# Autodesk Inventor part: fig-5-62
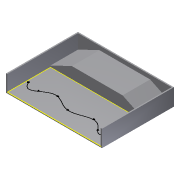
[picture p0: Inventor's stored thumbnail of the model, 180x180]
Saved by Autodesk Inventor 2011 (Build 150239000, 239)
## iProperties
Created: 2004-05
Part Number: fig-5-62
Document SubType Name: Modeling
Designer: CADCIM Technologies
Manufacturer: Standard
Standards Organization: Custom
Density: 1 g/cm^3
Author: CADCIM Technologies
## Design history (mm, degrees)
sketch "Sketch1"
  geometry: L1 (-40, -30)-(40, -30); L2 (40, -30)-(40, 30); L3 (40, 30)-(-40, 30); L4 (-40, 30)-(-40, -30); 1 further point
  constraints: 8 end point, 2 parallel, 1 horizontal, 1 perpendicular, 1 other
  dimensions: "d0" = 80 distance of L1.start L1.end; "d1" = 60 distance of L3.end L1.start; "d2" = 30 distance from line of point (0, 0) L1; "d3" = 40 distance from line of point (0, 0) L4
extrude "Extrusion1" new body sketch "Sketch1" distance "d4" = 14; taper "d5" = 0 deg
shell "Shell1" dims "d6" = 1
workplane "Work Plane1"
sketch "Sketch2"
  geometry: L1 (78, -13)-(78, -11.813); L2 (0, -11.813)-(0, -13); L3 (0, -13)-(78, -13); L4 (0, -11.813)-(17.826, -3.295); L5 (17.826, -3.295)-(60.174, -3.295); L6 (60.174, -3.295)-(78, -11.813); L7 (79, -13.795)-(78, -13.795); L8 (78, 0)-(78, -13) reference; L9 (0, -13)-(0, 0) reference; L10 (78, -13)-(0, -13) reference
  constraints: 14 end point, 3 collinear, 2 equal length, 2 vertical, 1 horizontal alignment, 1 parallel, 1 point on line
extrude "Extrusion2" join sketch "Sketch2" stored distance "d8" = 14; taper "d9" = 0 deg
workplane "Work Plane2"
sketch "Sketch4"
  geometry: L1 (78, 36)-(0, 36) reference; L2 (0, 36)-(0, 0) reference; L3 (78, 0)-(0, 0) reference; L4 (78, 0)-(78, 36) reference; 7 further points
  constraints: 7 other
body "Solid1"
other parameters: "d7" = 23, "d18" = 4
